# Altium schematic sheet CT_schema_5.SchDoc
size 299 x 185 mm
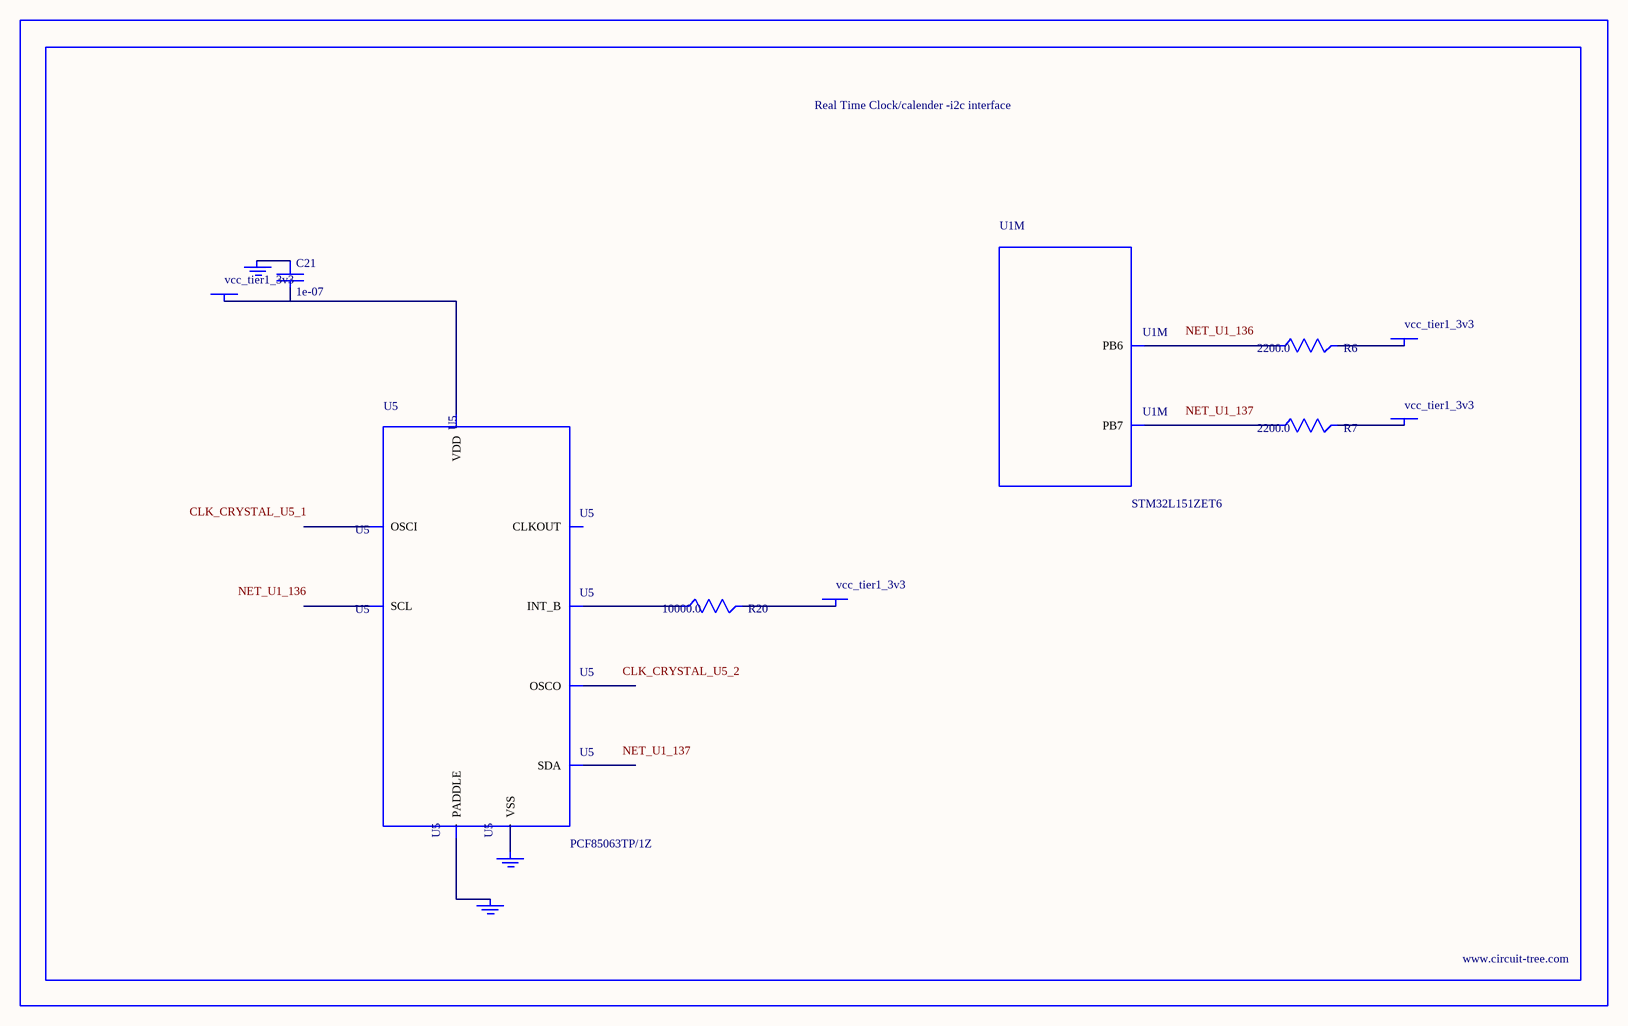
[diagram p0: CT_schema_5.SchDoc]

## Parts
BORDER4  (no value)
C21  1e-07  [C0402]
GND_INSTANCE_4_0  (no value)
GND_INSTANCE_4_1  (no value)
GND_INSTANCE_4_2  (no value)
POWER_INSTANCE_4_0  vcc_tier1_3v3
POWER_INSTANCE_4_1  vcc_tier1_3v3
POWER_INSTANCE_4_2  vcc_tier1_3v3
POWER_INSTANCE_4_3  vcc_tier1_3v3
R6  2200.0  [R0603]
R7  2200.0  [R0603]
R20  10000.0  [R0603]
U1  STM32L151ZET6  [LQFP144]  (part M of 14)
U5  PCF85063TP/1Z  [SON-8]

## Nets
NetC21_1: C21.1 GND_INSTANCE_4_0.0(GND)
NetC21_2: C21.2 POWER_INSTANCE_4_1.0(PWR) U5.8(VDD)
NetGND_INSTANCE_4_1_0: GND_INSTANCE_4_1.0(GND) U5.PAD(PADDLE)
NetGND_INSTANCE_4_2_0: GND_INSTANCE_4_2.0(GND) U5.4(VSS)
NetPOWER_INSTANCE_4_0_0: POWER_INSTANCE_4_0.0(PWR) R20.2
NetPOWER_INSTANCE_4_2_0: POWER_INSTANCE_4_2.0(PWR) R6.2
NetPOWER_INSTANCE_4_3_0: POWER_INSTANCE_4_3.0(PWR) R7.2
NetR6_1: R6.1 U1.136(PB6)
NetR7_1: R7.1 U1.137(PB7)
NetR20_1: R20.1 U5.3(INT_B)

Not connected (* = marked no-connect by the designer): U5 1(OSCI) 2(OSCO) 5(SDA) 6(SCL) 7(CLKOUT)

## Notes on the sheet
- Labels drawn without touching a wire or pin: CLK_CRYSTAL_U5_1, CLK_CRYSTAL_U5_2, NET_U1_136, NET_U1_137

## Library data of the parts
BORDER4 = BORDER_PAGE4
C21 = C0402C104K3RACTU
GND_INSTANCE_4_0-GND_INSTANCE_4_2 = GND
POWER_INSTANCE_4_0-POWER_INSTANCE_4_3 = PWR
R6 R7 = RC0603JR-072K2L
R20 = RC0603JR-0710KL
